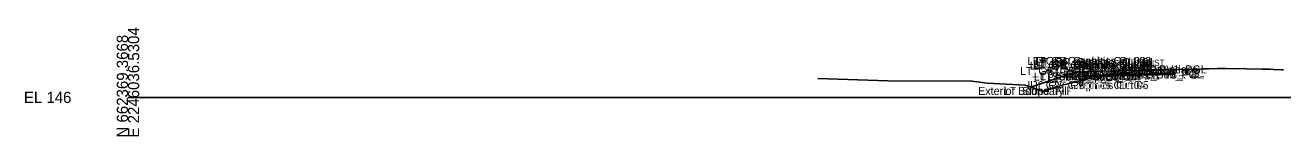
# Model space of a CAD drawing. Extents: x -26 to 603, y -10 to 9526.
# Drawn here: x -25.7 to 288.6, y 3490.3 to 3517.4 of the extents above; entities that cross this region are included whole.
import ezdxf

# ---------------------------------------------------------------- set-up
doc = ezdxf.new("R2010")
doc.units = 0
for name, color, linetype in [('Default', 7, 'Continuous'), ('Exist Cross Section Cell', 7, 'Continuous'), ('Exist XS Ground Line', 7, 'Continuous'), ('Prop CMT Guardrail Graphics', 7, 'Continuous'), ('Prop CMT Pvmt Course 1', 7, 'Continuous'), ('Prop CMT Pvmt Course 2', 7, 'Continuous'), ('Prop CMT Pvmt Course 3', 7, 'Continuous'), ('Prop CMT Pvmt Surface', 7, 'Continuous'), ('Prop CMT Pvmt Surface Shoulder', 7, 'Continuous'), ('Prop CMT Shld Paved Course 1', 7, 'Continuous'), ('Prop CMT Shld Paved Course 2', 7, 'Continuous'), ('Prop CMT Shld Paved Course 3', 7, 'Continuous'), ('Prop CMT Slope Grass', 7, 'Continuous'), ('Prop CMT Subgrade Earthwork', 7, 'Continuous'), ('Prop XS SE Text', 7, 'Continuous'), ('Prop XS Side Slope Text', 7, 'Continuous'), ('Scratch_Level_2', 7, 'Continuous')]:
    doc.layers.add(name, color=color, linetype=linetype)

msp = doc.modelspace()

# ---------------------------------------------------------------- linework, layer by layer
at = {"layer": 'Exist Cross Section Cell'}
msp.add_line((0, 3500), (300, 3500), dxfattribs=at)
at = {"layer": 'Exist XS Ground Line'}
for p, q in [((239.24, 3504.51), (243.55, 3505.21)), ((243.55, 3505.21), (244.75, 3505.38)), ((244.75, 3505.38), (251.24, 3506.43)), ((251.24, 3506.43), (251.92, 3506.5)), ((251.92, 3506.5), (255.15, 3506.66)), ((255.15, 3506.66), (257.41, 3506.79)), ((257.41, 3506.79), (258.44, 3506.79)), ((258.44, 3506.79), (258.77, 3506.9)), ((258.77, 3506.9), (259.41, 3506.92)), ((259.41, 3506.92), (261.32, 3506.97)), ((261.32, 3506.97), (262.91, 3506.99)), ((262.91, 3506.99), (266.48, 3507.06)), ((266.48, 3507.06), (268.4, 3507.1)), ((268.4, 3507.1), (270.26, 3507.15)), ((270.26, 3507.15), (272.41, 3507.2)), ((272.41, 3507.2), (273.27, 3507.21)), ((273.27, 3507.21), (274.04, 3507.22)), ((274.04, 3507.22), (274.36, 3507.21)), ((274.36, 3507.21), (279.49, 3507.12)), ((279.49, 3507.12), (283.46, 3507.06)), ((283.46, 3507.06), (284.37, 3507.02)), ((284.37, 3507.02), (285.36, 3507.01)), ((285.36, 3507.01), (286.33, 3506.96)), ((286.33, 3506.96), (288.48, 3506.86)), ((288.48, 3506.86), (288.79, 3506.84)), ((172.38, 3504.73), (189.94, 3504.14)), ((189.94, 3504.14), (210.9, 3504.07)), ((210.9, 3504.07), (214.75, 3503.56)), ((214.75, 3503.56), (224.27, 3503.04)), ((224.27, 3503.04), (225.43, 3502.76)), ((225.43, 3502.76), (228.66, 3501.5)), ((228.66, 3501.5), (231.29, 3502.39)), ((231.29, 3502.39), (231.95, 3502.6)), ((231.95, 3502.6), (238.13, 3504.2)), ((238.13, 3504.2), (239.24, 3504.51))]:
    msp.add_line(p, q, dxfattribs=at)
at = {"layer": 'Prop CMT Guardrail Graphics'}
for points in [[(237.89, 3502.93), (237.89, 3508.93)], [(237.89, 3508.93), (239.22, 3508.93), (239.49, 3508.64)], [(239.49, 3508.05), (239.22, 3507.76), (238.55, 3507.76)], [(239.49, 3508.64), (239.22, 3508.34)], [(239.22, 3508.34), (239.49, 3508.05)], [(238.55, 3507.76), (238.55, 3502.93)], [(238.55, 3502.93), (237.89, 3502.93)]]:
    msp.add_lwpolyline(points, dxfattribs=at)
at = {"layer": 'Prop CMT Pvmt Course 1'}
for points in [[(261.32, 3506.97), (249.5, 3506.68)], [(249.5, 3506.68), (249.5, 3505.76)], [(249.5, 3505.76), (261.32, 3506.06)], [(261.32, 3506.06), (261.32, 3506.97)]]:
    msp.add_lwpolyline(points, dxfattribs=at)
at = {"layer": 'Prop CMT Pvmt Course 2'}
for points in [[(261.32, 3506.06), (249.5, 3505.76)], [(249.5, 3505.76), (249.5, 3505.43)], [(249.5, 3505.43), (261.32, 3505.72)], [(261.32, 3505.72), (261.32, 3506.06)]]:
    msp.add_lwpolyline(points, dxfattribs=at)
at = {"layer": 'Prop CMT Pvmt Course 3'}
for points in [[(261.32, 3505.72), (249.5, 3505.43)], [(249.5, 3505.43), (261.32, 3505.72)], [(249.5, 3505.43), (249.5, 3505.43)], [(261.32, 3505.72), (261.32, 3505.72)]]:
    msp.add_lwpolyline(points, dxfattribs=at)
at = {"layer": 'Prop CMT Pvmt Surface'}
msp.add_lwpolyline([(261.32, 3506.97), (249.5, 3506.68)], dxfattribs=at)
at = {"layer": 'Prop CMT Pvmt Surface Shoulder'}
msp.add_lwpolyline([(249.5, 3506.68), (239.49, 3506.43)], dxfattribs=at)
at = {"layer": 'Prop CMT Shld Paved Course 1'}
for p, q in [((239.49, 3506.43), (238.55, 3505.49)), ((249.5, 3506.68), (245.5, 3506.58))]:
    msp.add_line(p, q, dxfattribs=at)
for points in [[(244.56, 3505.64), (249.5, 3505.76)], [(249.5, 3505.76), (249.5, 3506.68)]]:
    msp.add_lwpolyline(points, dxfattribs=at)
at = {"layer": 'Prop CMT Shld Paved Course 2'}
for p, q in [((238.55, 3505.49), (238.21, 3505.15)), ((249.5, 3505.76), (238.55, 3505.49))]:
    msp.add_line(p, q, dxfattribs=at)
for points in [[(244.22, 3505.3), (249.5, 3505.43)], [(249.5, 3505.43), (249.5, 3505.76)]]:
    msp.add_lwpolyline(points, dxfattribs=at)
at = {"layer": 'Prop CMT Shld Paved Course 3'}
for points in [[(249.5, 3505.43), (244.22, 3505.3), (243.72, 3505.28)], [(243.72, 3505.28), (249.5, 3505.43)], [(243.72, 3505.28), (243.72, 3505.28)], [(249.5, 3505.43), (249.5, 3505.43)]]:
    msp.add_lwpolyline(points, dxfattribs=at)
at = {"layer": 'Prop CMT Slope Grass'}
for points in [[(236.49, 3506.19), (225.79, 3502.62)], [(239.49, 3506.43), (236.49, 3506.19)]]:
    msp.add_lwpolyline(points, dxfattribs=at)
at = {"layer": 'Prop CMT Subgrade Earthwork'}
for points in [[(243.72, 3505.28), (232.97, 3505.02)], [(249.5, 3505.43), (243.72, 3505.28)], [(261.32, 3505.72), (249.5, 3505.43)]]:
    msp.add_lwpolyline(points, dxfattribs=at)

# ---------------------------------------------------------------- texts
at = {"layer": 'Default'}
msp.add_text('-', height=0.0001, dxfattribs=at).set_placement((0, 3500))
msp.add_text('-', height=0.0001, dxfattribs=at).set_placement((0, 3500))
msp.add_text('-', height=0.0001, dxfattribs=at).set_placement((0, 3500))
msp.add_text('-', height=0.0001, dxfattribs=at).set_placement((0, 3500))
at = {"layer": 'Exist Cross Section Cell'}
for s, p in [('E 2246036.5304', (2.8, 3490)), ('N 662369.3668', (0, 3490))]:
    msp.add_text(s, height=2.8, rotation=90, dxfattribs=at).set_placement(p)
msp.add_text('EL 146', height=2.8, dxfattribs=at).set_placement((-26, 3498.6))
at = {"layer": 'Prop XS SE Text'}
msp.add_text('EXIST', height=1.5, rotation=1.4321, dxfattribs=at).set_placement((253.27, 3507.77))
at = {"layer": 'Prop XS Side Slope Text'}
msp.add_text('3:1', height=1.5, rotation=18.4332, dxfattribs=at).set_placement((230.33, 3504.74))
at = {"layer": 'Scratch_Level_2'}
for s, p in [('LT_GR_Graphics Out 03', (224.78, 3508.08)), ('LT_GR_Graphics Out 06', (225.4, 3506.91)), ('LT_GR_Graphics Out 02', (226.12, 3508.08)), ('LT_GR_Graphics Out 09', (226.12, 3507.49)), ('LT_GR_Graphics Out 07', (226.12, 3506.91)), ('LT_GR_Graphics Out 08', (226.39, 3507.2)), ('LT_GR_Graphics Out 01', (226.95, 3507.79)), ('Exterior Boundary', (245.46, 3505.97)), ('LT_PV1_PGL', (253.1, 3505.97)), ('LT_GS_OS_GR_Face_Graphics', (222.95, 3505.58)), ('LT_Sub_OSS_DLT', (226.38, 3504.17)), ('LT_Sub_Trench_Out', (227.92, 3504.28)), ('LT_PS3_Shelf_Out', (229.7, 3504.28)), ('LT_GS_OS_CTL', (231.86, 3505.34)), ('LT_PS3_OEOP', (234.46, 3504.3)), ('LT_PS2_OEOP', (234.8, 3504.64)), ('LT_PS1_OEOP', (236.3, 3505.58)), ('LT_Sub_OEOT', (239.58, 3504.43)), ('LT_PV2_OEOT', (239.67, 3504.76)), ('LT_PV3_OEOT', (239.67, 3504.43)), ('LT_PV1_OEOT', (240.24, 3505.68)), ('LT_Sub_PGL', (252.44, 3504.72)), ('LT_PV2_PGL', (252.53, 3505.06)), ('LT_PV3_PGL', (252.53, 3504.72)), ('Exterior Boundary', (212.49, 3500.62)), ('Exterior Boundary', (212.49, 3500.62)), ('LT_Slope_Fill', (218.86, 3500.62)), ('LT_Slope_Fill', (218.86, 3500.62)), ('LT_GR_Graphics Out 04', (224.78, 3502.08)), ('LT_GR_Graphics Out 05', (225.45, 3502.08))]:
    msp.add_text(s, height=2, dxfattribs=at).set_placement(p)

doc.saveas('drawing.dxf')
